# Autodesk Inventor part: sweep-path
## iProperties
Created: 2006-01
Part Number: sweep-path
Document SubType Name: Modeling
Designer: CADCIM
Density: 1 g/cm^3
Author: CADCIM
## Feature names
1. Sweep3
